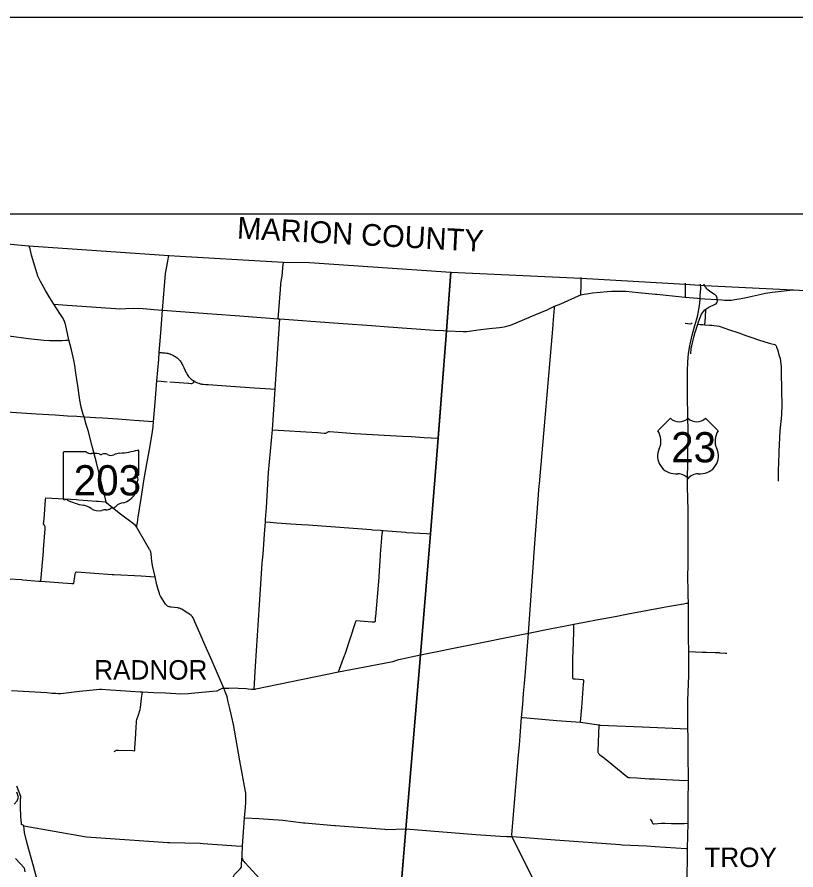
# Model space of a CAD drawing. Extents: x 1729596 to 1925846, y 659247 to 911751.
# Drawn here: x 1777664 to 1813555, y 860705 to 899996 of the extents above; entities that cross this region are included whole.
import ezdxf

# ---------------------------------------------------------------- set-up
doc = ezdxf.new("R2010")
doc.units = 0
for name, color, linetype in [('GM_X_Adjacent_County_Text', 7, 'Continuous'), ('GM_X_County', 7, 'Continuous'), ('GM_X_County_Road', 7, 'Continuous'), ('GM_X_State_Route', 7, 'Continuous'), ('GM_X_State_Shield', 7, 'Continuous'), ('GM_X_Township', 7, 'Continuous'), ('GM_X_Township_Road', 7, 'Continuous'), ('GM_X_Township_Text', 7, 'Continuous'), ('GM_X_US_Route', 7, 'Continuous'), ('GM_X_US_Shield', 7, 'Continuous'), ('SC_Scratch1', 7, 'Continuous'), ('SH_Data', 7, 'Continuous')]:
    doc.layers.add(name, color=color, linetype=linetype)

msp = doc.modelspace()

# ---------------------------------------------------------------- linework, layer by layer
at = {"layer": 'GM_X_County'}
msp.add_lwpolyline([(1776032, 889658), (1778209, 889456), (1784657, 889014), (1789933, 888711), (1791146, 888682), (1797651, 888237), (1803655, 887971), (1808445, 887685), (1809126, 887642), (1809339, 887629), (1813443, 887429), (1813717, 887422)], dxfattribs=at)
at = {"layer": 'GM_X_County_Road'}
for points in [[(1783164, 876512), (1783184, 876554), (1783209, 876711), (1783243, 876961), (1783384, 877811), (1783523, 878729), (1783651, 879411), (1783765, 880071), (1783893, 880796), (1783932, 881116), (1783954, 881366), (1784027, 882233), (1784112, 883231), (1784194, 884219), (1784219, 884544), (1784290, 885451), (1784371, 886499), (1784505, 888183), (1784615, 888751), (1784662, 889026)], [(1789695, 886094), (1789719, 886480), (1789799, 887439), (1789813, 887710), (1789851, 887912), (1789876, 888066), (1789915, 888443), (1789938, 888712)], [(1802428, 886671), (1802725, 886790), (1803530, 887161), (1803639, 887203), (1803789, 887229), (1804010, 887263), (1804184, 887296), (1804528, 887326), (1804861, 887359), (1805077, 887369), (1805715, 887362), (1806296, 887312), (1806604, 887281), (1807079, 887231), (1807143, 887228), (1808298, 887102), (1808443, 887089)], [(1779364, 886770), (1779967, 886729), (1781087, 886653), (1782198, 886565), (1782396, 886560), (1782670, 886574), (1783048, 886584), (1783473, 886564), (1783964, 886527), (1784371, 886499), (1786660, 886325), (1787926, 886227), (1788905, 886151), (1789695, 886094), (1789778, 886088), (1790812, 886013), (1791205, 885983), (1792690, 885877), (1793992, 885783), (1794775, 885730), (1796902, 885573), (1797304, 885549), (1797451, 885547), (1797502, 885545)], [(1797502, 885545), (1798225, 885516), (1798393, 885518), (1798918, 885581), (1799416, 885645), (1799891, 885700), (1800108, 885729), (1800227, 885756), (1800345, 885789), (1800404, 885808), (1800482, 885836), (1801245, 886152), (1801314, 886180), (1802090, 886513), (1802428, 886671)], [(1801484, 875131), (1801730, 878401), (1801736, 878492), (1802364, 885806), (1802368, 885867), (1802423, 886605), (1802428, 886671)], [(1788586, 869035), (1788657, 870095), (1788840, 872922), (1788956, 874843), (1789001, 875254), (1789063, 876180), (1789105, 876736), (1789110, 876852), (1789151, 877401), (1789258, 879010), (1789428, 880980), (1789558, 882861), (1789778, 886088)], [(1774404, 882033), (1774406, 882032), (1774523, 881989), (1774565, 881978), (1774598, 881976), (1774681, 881977), (1777408, 881796), (1778560, 881723), (1779427, 881668), (1779984, 881633), (1780423, 881605), (1780749, 881582)], [(1801238, 871613), (1801481, 875086), (1801483, 875120), (1801484, 875131)], [(1796250, 870609), (1800830, 871534), (1801238, 871613), (1802216, 871813), (1802942, 871947), (1803327, 872024), (1803819, 872121), (1804436, 872238), (1805225, 872387), (1805820, 872499), (1807386, 872793), (1807725, 872855), (1808371, 872970), (1808499, 872991), (1808602, 872989)], [(1801567, 856755), (1801567, 856755), (1801584, 856930), (1801742, 859524), (1801746, 859662), (1801732, 859727), (1801677, 859846), (1801556, 860087), (1800489, 862190), (1800471, 862240), (1800469, 862342), (1800776, 866006), (1800811, 866452), (1800848, 866888), (1800911, 867730), (1800965, 868323), (1801008, 868838), (1801046, 869299), (1801092, 869835), (1801238, 871613)], [(1787196, 869081), (1787270, 869083), (1787417, 869086), (1787765, 869087), (1787850, 869078), (1788227, 869057), (1788320, 869047), (1788464, 869034), (1788586, 869035), (1788632, 869037), (1788663, 869041), (1792472, 869834), (1794909, 870293), (1794974, 870307), (1795260, 870400), (1796250, 870609)], [(1777415, 868976), (1778218, 868930), (1779038, 868876), (1779266, 868856), (1779449, 868845), (1779563, 868837), (1779670, 868838), (1779800, 868851), (1780050, 868882), (1780545, 868937), (1781023, 868994), (1781326, 869024), (1781460, 869035), (1781558, 869036), (1781964, 869008), (1782895, 868945), (1783343, 868918), (1783443, 868912), (1783964, 868885), (1784505, 868858), (1785211, 868814), (1785566, 868838), (1785696, 868848), (1786172, 868888), (1786688, 868934), (1786854, 868955), (1786890, 868963), (1787000, 869020), (1787134, 869073), (1787163, 869079), (1787196, 869081)], [(1779569, 856584), (1779019, 858639), (1778669, 859959), (1778417, 860876), (1778136, 861918), (1778010, 862427), (1777970, 862741)], [(1777970, 862741), (1780778, 862248), (1780868, 862232), (1784609, 861971), (1784696, 861964), (1786106, 861939), (1786241, 861929)], [(1786241, 861929), (1787766, 861819), (1788057, 861796)], [(1786675, 855044), (1786697, 856311), (1786698, 856387), (1786835, 857221), (1786845, 857279), (1786936, 858914), (1786940, 858987), (1787642, 860408), (1787683, 860493), (1787941, 860759), (1788006, 860826), (1788012, 861039), (1788018, 861131), (1788033, 861371)]]:
    msp.add_lwpolyline(points, dxfattribs=at)
at = {"layer": 'GM_X_State_Route'}
for points in [[(1787196, 869081), (1786647, 870325), (1786268, 871186), (1786147, 871471), (1785858, 872136), (1785789, 872293), (1785775, 872319), (1785743, 872367), (1785725, 872389), (1785686, 872432), (1785615, 872488), (1785462, 872585), (1785254, 872712), (1785207, 872738), (1785156, 872758), (1785130, 872765), (1785104, 872771), (1785078, 872776), (1784764, 872817), (1784743, 872818), (1784699, 872825), (1784673, 872831), (1784633, 872843), (1784596, 872861), (1784578, 872873), (1784561, 872885), (1784531, 872913), (1784502, 872951), (1784275, 873322), (1784260, 873348), (1784235, 873404), (1784225, 873433), (1784211, 873480), (1784162, 873624), (1784100, 873843), (1784021, 874208), (1783910, 874738), (1783876, 874927), (1783859, 875086), (1783838, 875289), (1783833, 875317), (1783827, 875344), (1783809, 875398), (1783786, 875450), (1783772, 875475), (1783588, 875783), (1783232, 876403), (1783164, 876512), (1783115, 876570), (1783035, 876646), (1782427, 877101), (1781907, 877510), (1781873, 877541), (1781822, 877589), (1781780, 877630), (1781764, 877670), (1781516, 878719), (1781330, 879483), (1781130, 880233), (1780935, 880943), (1780851, 881229), (1780749, 881582), (1780714, 881694), (1780668, 881862), (1780620, 882022), (1780562, 882353), (1780462, 883009), (1780418, 883294), (1780375, 883601), (1780321, 883942), (1780275, 884187), (1780166, 884660), (1780054, 885130), (1779891, 885844), (1779879, 885886), (1779851, 885966), (1779818, 886043), (1779756, 886154), (1779666, 886298), (1779364, 886770), (1779176, 887069), (1778977, 887392), (1778738, 887817), (1778667, 887962), (1778627, 888061), (1778487, 888517), (1778336, 889030), (1778262, 889312), (1778237, 889390), (1778211, 889454)], [(1808448, 887738), (1808450, 887411), (1808443, 887089)], [(1809140, 887038), (1809351, 887019), (1809932, 886979), (1810132, 886963), (1810262, 886956), (1810420, 886950), (1810584, 886956), (1810738, 886979), (1811036, 887037), (1811335, 887099), (1811536, 887144), (1811949, 887231), (1812149, 887270), (1812265, 887288), (1812452, 887318), (1813005, 887387), (1813408, 887426)], [(1813408, 887426), (1813443, 887429), (1813717, 887422), (1814360, 887388), (1814824, 887360)], [(1808443, 887089), (1808443, 887089), (1809011, 887047), (1809140, 887038)], [(1787564, 867736), (1787470, 868147), (1787382, 868515), (1787358, 868624), (1787327, 868731), (1787290, 868838), (1787196, 869081)], [(1788847, 860293), (1788174, 861037), (1788137, 861075), (1788121, 861096), (1788106, 861118), (1788089, 861147), (1788079, 861165), (1788068, 861189), (1788050, 861239), (1788039, 861291), (1788033, 861371), (1788057, 861796), (1788151, 863108), (1788185, 863584), (1788200, 863823), (1788208, 864005), (1788211, 864101), (1788210, 864149), (1788208, 864198), (1788204, 864245), (1788195, 864319), (1787933, 865736), (1787806, 866433), (1787687, 867143), (1787639, 867409), (1787564, 867736)]]:
    msp.add_lwpolyline(points, dxfattribs=at)
at = {"layer": 'GM_X_State_Shield'}
for p, q in [((1779789, 879923), (1779789, 877810)), ((1779789, 879923), (1779789, 877810)), ((1780843, 879960), (1779823, 879960)), ((1780843, 879960), (1779823, 879960)), ((1783269, 878907), (1783269, 880012)), ((1783269, 878907), (1783269, 880012)), ((1783269, 878907), (1783269, 878907)), ((1783269, 878907), (1783269, 878907))]:
    msp.add_line(p, q, dxfattribs=at)
for centre, major_axis, start_param, end_param in [((1779829, 879928), (40.3, 0), 1.712693, 3.28349), ((1779829, 879928), (40.3, 0), 1.712693, 3.28349), ((1781085, 880205), (391, 0), 4.042523, 4.731795), ((1781085, 880205), (391, 0), 4.042523, 4.731795), ((1781215, 878773), (1404, 0), 1.404758, 1.657858), ((1781215, 878773), (1404, 0), 1.404758, 1.657858), ((1781534, 879939), (113, 0), 3.836095, 5.185415), ((1781534, 879939), (113, 0), 3.836095, 5.185415), ((1781699, 879694), (235, 0), 0.950623, 2.079405), ((1781699, 879694), (235, 0), 0.950623, 2.079405), ((1782002, 880030), (282, 0), 4.081561, 5.145723), ((1782002, 880030), (282, 0), 4.081561, 5.145723), ((1782500, 879314), (743, 0), 1.699011, 2.107814), ((1782500, 879314), (743, 0), 1.699011, 2.107814), ((1782030, 882841), (3691, 0), 4.814394, 5.042369), ((1782030, 882841), (3691, 0), 4.814394, 5.042369), ((1783231, 880017), (38.7, 0), 6.141152, 7.989035), ((1783231, 880017), (38.7, 0), 6.141152, 7.989035), ((1783408, 878444), (262, 0), 2.387724, 3.262537), ((1783408, 878444), (262, 0), 2.387724, 3.262537), ((1783260, 878825), (60, 0), 1.883978, 3.671073), ((1783260, 878825), (60, 0), 1.883978, 3.671073), ((1782879, 878686), (360, 0), 5.934695, 6.695948), ((1782879, 878686), (360, 0), 5.934695, 6.695948), ((1783228, 878902), (41.5, 0), 5.05454, 6.418171), ((1783228, 878902), (41.5, 0), 5.05454, 6.418171), ((1782236, 878303), (923, 0), 5.101752, 6.440018), ((1782236, 878303), (923, 0), 5.101752, 6.440018), ((1779829, 877805), (40.7, 0), 3.00124, 4.508301), ((1779829, 877805), (40.7, 0), 3.00124, 4.508301), ((1779835, 878022), (310, 0), 4.665946, 4.897461), ((1779835, 878022), (310, 0), 4.665946, 4.897461), ((1779899, 877688), (112, 0), 0.519207, 1.627899), ((1779899, 877688), (112, 0), 0.519207, 1.627899), ((1781312, 879587), (2665, 0), 4.195997, 4.488961), ((1781312, 879587), (2665, 0), 4.195997, 4.488961), ((1780518, 876861), (834, 0), 0.823519, 1.323587), ((1780518, 876861), (834, 0), 0.823519, 1.323587), ((1782019, 877315), (79.4, 0), 1.147584, 2.315152), ((1782019, 877315), (79.4, 0), 1.147584, 2.315152), ((1781985, 877605), (298, 0), 4.937069, 5.64225), ((1781985, 877605), (298, 0), 4.937069, 5.64225), ((1782626, 877217), (506, 0), 1.647645, 2.488434), ((1782626, 877217), (506, 0), 1.647645, 2.488434), ((1781419, 877678), (529, 0), 4.026481, 4.996735), ((1781419, 877678), (529, 0), 4.026481, 4.996735), ((1781725, 876947), (435, 0), 1.495662, 1.94098), ((1781725, 876947), (435, 0), 1.495662, 1.94098), ((1781764, 877519), (282, 0), 4.691044, 5.507374), ((1781764, 877519), (282, 0), 4.691044, 5.507374)]:
    msp.add_ellipse(centre, major_axis=major_axis, ratio=0.8, start_param=start_param, end_param=end_param, dxfattribs=at)
at = {"layer": 'GM_X_Township'}
for points in [[(1797651, 888237), (1797451, 885547), (1797071, 880600), (1796711, 876185), (1796651, 875449), (1796250, 870609), (1795573, 862604), (1795247, 858499)], [(1777527, 863741), (1777673, 863892), (1777723, 864054), (1777660, 864284)], [(1778036, 860617), (1778010, 860785), (1777585, 861235)]]:
    msp.add_lwpolyline(points, dxfattribs=at)
at = {"layer": 'GM_X_Township_Road'}
for points in [[(1797103, 881017), (1797451, 885547), (1797658, 888259)], [(1803639, 887203), (1803654, 887676), (1803660, 888000)], [(1809932, 886979), (1809918, 887050), (1809907, 887094), (1809888, 887135), (1809878, 887151), (1809840, 887193), (1809801, 887219), (1809584, 887360), (1809495, 887435), (1809449, 887480), (1809413, 887519), (1809392, 887551), (1809310, 887690)], [(1808984, 885705), (1809011, 885796), (1809034, 885855), (1809061, 885951), (1809170, 886226), (1809206, 886304), (1809251, 886376), (1809294, 886437), (1809358, 886504), (1809406, 886542), (1809454, 886576), (1809542, 886627), (1809831, 886763), (1809881, 886792), (1809913, 886825), (1809931, 886870), (1809935, 886910), (1809932, 886979)], [(1809386, 886211), (1809409, 886473), (1809406, 886542)], [(1809364, 885824), (1809383, 886171), (1809386, 886211)], [(1808454, 885901), (1808566, 885881), (1808684, 885871), (1808743, 885873), (1808777, 885905)], [(1808714, 884485), (1808722, 884731), (1808722, 884738), (1808750, 884850), (1808872, 885317), (1808915, 885473), (1808938, 885554), (1808984, 885705)], [(1809034, 885855), (1809142, 885837), (1809263, 885827), (1809364, 885824), (1809568, 885807), (1809684, 885798), (1809773, 885791), (1809914, 885774), (1810011, 885752), (1810278, 885666), (1810454, 885608), (1810925, 885443), (1811247, 885331), (1811523, 885237)], [(1775741, 885463), (1776426, 885437), (1776777, 885403), (1776902, 885381), (1777004, 885378), (1777125, 885372), (1777289, 885315), (1778196, 885185), (1778905, 885114), (1779153, 885103), (1779444, 885093), (1779746, 885100), (1779909, 885109), (1779987, 885117), (1780054, 885130)], [(1811523, 885237), (1811827, 885133), (1812317, 884973), (1812441, 884940), (1812528, 884920), (1812580, 884904), (1812610, 884886), (1812639, 884853), (1812664, 884782), (1812698, 884680), (1812730, 884568), (1812770, 884428), (1812820, 884266), (1812840, 884152), (1812859, 883988), (1812870, 883884), (1812870, 883618), (1812883, 882825), (1812883, 882752), (1812905, 882162), (1812885, 881655), (1812818, 880932), (1812765, 879975), (1812762, 879888), (1812743, 879096), (1812732, 878621)], [(1784219, 884544), (1784275, 884542), (1784330, 884538), (1784387, 884534), (1784447, 884529), (1784491, 884526), (1784544, 884519), (1784576, 884515), (1784610, 884507), (1784645, 884498), (1784687, 884486), (1784724, 884474), (1784769, 884457), (1784812, 884440), (1784875, 884406), (1784925, 884377), (1784951, 884362), (1785001, 884324), (1785043, 884292), (1785085, 884253), (1785121, 884218), (1785146, 884188), (1785177, 884152), (1785205, 884114), (1785227, 884081), (1785255, 884038), (1785278, 883997), (1785307, 883937), (1785343, 883856), (1785390, 883751), (1785417, 883692), (1785443, 883636), (1785467, 883591), (1785486, 883555), (1785505, 883524), (1785531, 883487), (1785569, 883438), (1785608, 883393), (1785656, 883346), (1785690, 883316), (1785736, 883281), (1785782, 883246), (1785833, 883216), (1785864, 883197), (1785902, 883180), (1785935, 883164), (1785984, 883144), (1786034, 883126), (1786072, 883114), (1786104, 883105), (1786151, 883095), (1786182, 883089), (1786246, 883080), (1786362, 883072), (1786468, 883065)], [(1784112, 883231), (1784306, 883215), (1784581, 883194)], [(1784699, 883186), (1785349, 883138), (1785566, 883125), (1785579, 883124)], [(1785579, 883124), (1785689, 883117), (1785701, 883119), (1785723, 883121), (1785749, 883131), (1785773, 883145), (1785790, 883160), (1785812, 883183), (1785833, 883216)], [(1786468, 883065), (1787514, 882996), (1788607, 882920), (1789343, 882874), (1789558, 882861)], [(1780749, 881582), (1781033, 881565), (1781283, 881552), (1781619, 881527), (1782312, 881487), (1783082, 881429), (1783715, 881383), (1783954, 881366)], [(1789428, 880980), (1791504, 880851), (1791817, 880828), (1791839, 880826), (1791855, 880827), (1791888, 880833), (1791918, 880845), (1791949, 880865), (1791974, 880882), (1792002, 880893), (1792031, 880898), (1792061, 880897), (1792264, 880882), (1793223, 880818), (1794577, 880731), (1795429, 880687), (1795818, 880667), (1796427, 880633), (1797071, 880600)], [(1796651, 875448), (1796651, 875449), (1796711, 876185), (1797071, 880600), (1797103, 881017)], [(1778760, 874006), (1778875, 875382), (1778882, 875465), (1778952, 876413), (1778959, 876509), (1778911, 876603), (1778883, 876655), (1778897, 876760), (1778909, 876862), (1778976, 877757), (1778983, 877852), (1780406, 877766), (1780489, 877760), (1781332, 877695), (1781408, 877688), (1781724, 877665), (1781764, 877670)], [(1789105, 876736), (1789321, 876723), (1789630, 876700), (1790280, 876655), (1790776, 876623), (1791098, 876602), (1792537, 876504), (1793982, 876384), (1794039, 876380), (1794407, 876352), (1794506, 876344), (1794538, 876342)], [(1792472, 869834), (1792760, 870585), (1792779, 870645), (1793264, 872097), (1793296, 872196), (1794034, 872141), (1794103, 872136), (1794143, 872138), (1794179, 872172), (1794188, 872330), (1794191, 872388), (1794344, 874177), (1794349, 874238), (1794412, 875187), (1794416, 875256), (1794476, 875993), (1794480, 876052), (1794499, 876262), (1794506, 876344)], [(1794538, 876342), (1795556, 876259), (1795631, 876252), (1796527, 876197), (1796711, 876185)], [(1796250, 870609), (1796651, 875448)], [(1778734, 874009), (1778760, 874006), (1778766, 874006), (1780188, 873906), (1780264, 873900), (1780288, 873916), (1780344, 874335), (1780352, 874393), (1780370, 874430), (1780414, 874432), (1782047, 874317), (1782140, 874310), (1783379, 874247), (1784021, 874208)], [(1777112, 873891), (1777129, 873941), (1777152, 874011), (1777174, 874061), (1777204, 874087), (1777296, 874115), (1777876, 874078), (1777937, 874074), (1778674, 874014), (1778730, 874009), (1778734, 874009)], [(1803268, 870443), (1803301, 871169), (1803323, 871703), (1803327, 872024)], [(1808615, 870762), (1809236, 870737), (1809316, 870737), (1809432, 870743), (1809843, 870725), (1810007, 870717), (1810039, 870714), (1810063, 870708), (1810302, 870697), (1810369, 870694)], [(1795573, 862604), (1796250, 870609)], [(1803630, 867510), (1803691, 868196), (1803773, 869260), (1803782, 869375), (1803783, 869405), (1803781, 869425), (1803775, 869439), (1803764, 869452), (1803746, 869464), (1803713, 869468), (1803374, 869487), (1803312, 869492), (1803294, 869504), (1803281, 869529), (1803275, 869558), (1803280, 869733), (1803274, 869853), (1803267, 870424), (1803268, 870443)], [(1782133, 866169), (1782246, 866221), (1782316, 866230), (1782999, 866203), (1783063, 866198), (1783088, 866215), (1783098, 866319), (1783138, 866969), (1783144, 867025), (1783155, 867257), (1783164, 867523), (1783171, 867568), (1783190, 867631), (1783256, 867847), (1783339, 868104), (1783356, 868188), (1783405, 868604), (1783443, 868912)], [(1800911, 867730), (1800986, 867727), (1801330, 867699), (1802540, 867596), (1803630, 867510), (1804477, 867384), (1804498, 867383), (1804527, 867381)], [(1804477, 867384), (1804421, 866175), (1804424, 866127), (1804449, 866069), (1804513, 866012), (1804732, 865849), (1805503, 865225), (1805691, 865068), (1805810, 864983), (1805846, 864967), (1805905, 864963), (1806229, 864943), (1806794, 864904), (1807037, 864899), (1807575, 864865), (1808185, 864842), (1808605, 864823)], [(1804527, 867381), (1806474, 867297)], [(1806474, 867297), (1808579, 867207)], [(1777970, 862741), (1777923, 862765), (1777865, 862795), (1777848, 863058), (1777843, 863124), (1777826, 863652), (1777823, 863735), (1777822, 863788), (1777819, 863869), (1777829, 863974), (1777835, 864032), (1777835, 864085), (1777760, 864282), (1777729, 864364), (1777653, 864561)], [(1788151, 863108), (1788798, 863076), (1789909, 862999), (1790859, 862876), (1790920, 862871), (1792288, 862753), (1792341, 862749), (1794605, 862578), (1794706, 862571), (1795573, 862604)], [(1806832, 863051), (1806885, 862986), (1806910, 862940), (1806928, 862878), (1806946, 862853), (1806969, 862836), (1807015, 862834), (1807358, 862860), (1807384, 862860), (1807529, 862858), (1807823, 862841), (1807878, 862841), (1808114, 862844), (1808408, 862851), (1808584, 862855)], [(1795248, 858510), (1795573, 862604)], [(1795573, 862604), (1795573, 862604), (1798801, 862345), (1799934, 862267), (1800231, 862253), (1800471, 862240)], [(1800471, 862240), (1802462, 862095), (1805449, 861870), (1805545, 861864), (1806678, 861809), (1807065, 861779), (1808492, 861691), (1808564, 861690)]]:
    msp.add_lwpolyline(points, dxfattribs=at)
at = {"layer": 'GM_X_US_Route'}
for points in [[(1808684, 884925), (1808774, 885335), (1808893, 885780), (1808982, 886093), (1809032, 886266), (1809069, 886438), (1809101, 886628), (1809127, 886805), (1809140, 887038), (1809140, 887166), (1809178, 887493), (1809158, 887698)], [(1808573, 884088), (1808574, 884127), (1808608, 884480), (1808669, 884858), (1808684, 884925)], [(1808559, 883718), (1808573, 884088)], [(1808595, 873359), (1808593, 873477), (1808580, 874305), (1808584, 874680), (1808589, 875164), (1808584, 876236), (1808583, 877272), (1808564, 878356), (1808567, 879838), (1808589, 880869), (1808563, 882458), (1808556, 883637), (1808559, 883718)], [(1808574, 868253), (1808573, 868508), (1808622, 869660), (1808622, 869931), (1808615, 870762), (1808609, 871383), (1808606, 872500), (1808602, 872989), (1808595, 873359)], [(1808580, 867154), (1808579, 867207), (1808575, 868049), (1808574, 868253)], [(1808593, 863493), (1808595, 863872), (1808605, 864823), (1808590, 866059), (1808585, 866653), (1808583, 866893), (1808580, 867154)], [(1808531, 859016), (1808538, 859249), (1808549, 859969), (1808564, 861690), (1808584, 862855), (1808592, 863349), (1808593, 863493)]]:
    msp.add_lwpolyline(points, dxfattribs=at)
at = {"layer": 'GM_X_US_Shield'}
for p, q in [((1807768, 881512), (1807188, 880932)), ((1807768, 881512), (1807188, 880932)), ((1809972, 880932), (1809392, 881512)), ((1809972, 880932), (1809392, 881512)), ((1808000, 878960), (1808116, 878960)), ((1808000, 878960), (1808116, 878960)), ((1809044, 878960), (1809160, 878960)), ((1809044, 878960), (1809160, 878960))]:
    msp.add_line(p, q, dxfattribs=at)
for centre, radius, start, end in [((1808174, 881927), 580, 225.573, 314.427), ((1808174, 881927), 580, 225.573, 314.427), ((1808986, 881927), 580, 225.573, 314.427), ((1808986, 881927), 580, 225.573, 314.427), ((1806523, 880466), 812, 334.5471, 35.0009), ((1806523, 880466), 812, 334.5471, 35.0009), ((1810637, 880466), 812, 144.9991, 205.4529), ((1810637, 880466), 812, 144.9991, 205.4529), ((1807991, 879772), 812, 154.8319, 270.6383), ((1807991, 879772), 812, 154.8319, 270.6383), ((1809169, 879772), 812, 269.3617, 25.1681), ((1809169, 879772), 812, 269.3617, 25.1681), ((1808116, 878380), 580, 36.8699, 90), ((1808116, 878380), 580, 36.8699, 90), ((1809044, 878380), 580, 90, 143.1301), ((1809044, 878380), 580, 90, 143.1301)]:
    msp.add_arc(centre, radius, start, end, dxfattribs=at)
at = {"layer": 'SC_Scratch1'}
msp.add_lwpolyline([(1729596, 899996), (1925846, 899996), (1925846, 765496), (1729596, 765496)], close=True, dxfattribs=at)
at = {"layer": 'SH_Data'}
msp.add_line((1752099, 890928), (1828599, 890928), dxfattribs=at)

# ---------------------------------------------------------------- texts
at = {"layer": 'GM_X_Adjacent_County_Text'}
msp.add_text('MARION COUNTY', height=1000, rotation=356.9158, dxfattribs=at).set_placement((1787785, 889795))
at = {"layer": 'GM_X_State_Shield'}
msp.add_text('203', height=1392.2, dxfattribs=at).set_placement((1780274, 877959))
msp.add_text('203', height=1392.2, dxfattribs=at).set_placement((1780274, 877959))
at = {"layer": 'GM_X_Township_Text'}
for s, p in [('RADNOR', (1781221, 869472)), ('TROY', (1809335, 860835))]:
    msp.add_text(s, height=900, rotation=0, dxfattribs=at).set_placement(p)
at = {"layer": 'GM_X_US_Shield'}
msp.add_text('23', height=1392.2, dxfattribs=at).set_placement((1807805, 879482))
msp.add_text('23', height=1392.2, dxfattribs=at).set_placement((1807805, 879482))

doc.saveas('drawing.dxf')
